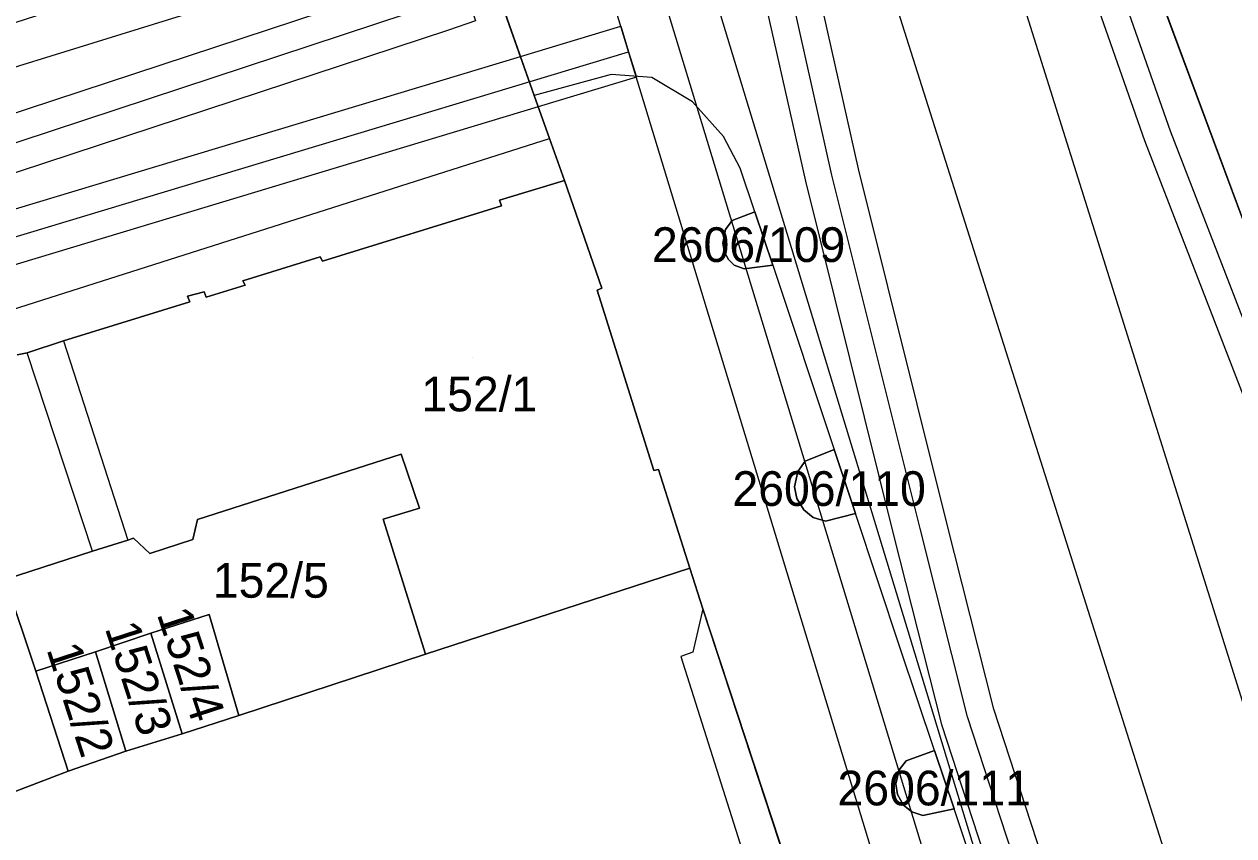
# Model space of a CAD drawing. Extents: x -263423 to -261326, y -1240067 to -1237864.
# Drawn here: x -262739.6 to -262669.9, y -1239931.7 to -1239884.9 of the extents above; entities that cross this region are included whole.
import ezdxf

# ---------------------------------------------------------------- set-up
doc = ezdxf.new("R2010")
doc.units = 0
for name, color, linetype in [('body_kn', 7, 'Continuous'), ('kladpar_druhypozemkov', 7, 'Continuous'), ('kladpar_hranice', 7, 'Continuous'), ('kladpar_parcelnecisla', 7, 'Continuous'), ('kladpar_plochy', 7, 'Continuous'), ('tarchy_linie', 7, 'Continuous'), ('zappar_hrandruhpozemk', 7, 'Continuous')]:
    doc.layers.add(name, color=color, linetype=linetype)

msp = doc.modelspace()

# ---------------------------------------------------------------- linework, layer by layer
at = {"layer": 'body_kn'}
for p, q in [((-262715.16, -1239885.25), (-262715.16, -1239885.25)), ((-262705.21, -1239885.03), (-262705.21, -1239885.03)), ((-262704.77, -1239886.5), (-262704.77, -1239886.5)), ((-262711.01, -1239886.77), (-262711.01, -1239886.77)), ((-262705.77, -1239887.81), (-262705.77, -1239887.81)), ((-262704.32, -1239887.97), (-262704.32, -1239887.97)), ((-262703.42, -1239887.99), (-262703.42, -1239887.99)), ((-262710.21, -1239889.03), (-262710.21, -1239889.03)), ((-262701.09, -1239889.38), (-262701.09, -1239889.38)), ((-262709.98, -1239889.68), (-262709.98, -1239889.68)), ((-262709.34, -1239891.5), (-262709.34, -1239891.5)), ((-262699.29, -1239891.39), (-262699.29, -1239891.39)), ((-262675.02, -1239891.62), (-262675.02, -1239891.62)), ((-262673.54, -1239891.07), (-262673.54, -1239891.07)), ((-262698.33, -1239893.21), (-262698.33, -1239893.21)), ((-262693.04, -1239893.61), (-262693.04, -1239893.61)), ((-262691.51, -1239893.25), (-262691.51, -1239893.25)), ((-262708.46, -1239893.93), (-262708.46, -1239893.93)), ((-262694.57, -1239893.97), (-262694.57, -1239893.97)), ((-262712.22, -1239895.06), (-262712.22, -1239895.06)), ((-262712.1, -1239895.38), (-262712.1, -1239895.38)), ((-262697.49, -1239895.73), (-262697.49, -1239895.73)), ((-262697.49, -1239895.73), (-262697.49, -1239895.73)), ((-262698.79, -1239896.22), (-262698.79, -1239896.22)), ((-262699.18, -1239896.75), (-262699.18, -1239896.75)), ((-262699.34, -1239897.54), (-262699.34, -1239897.54)), ((-262722.55, -1239898.33), (-262722.55, -1239898.33)), ((-262722.43, -1239898.58), (-262722.43, -1239898.58)), ((-262699.23, -1239898.06), (-262699.23, -1239898.06)), ((-262699, -1239898.48), (-262699, -1239898.48)), ((-262698.68, -1239898.8), (-262698.68, -1239898.8)), ((-262698.11, -1239899.02), (-262698.11, -1239899.02)), ((-262696.46, -1239898.81), (-262696.46, -1239898.81)), ((-262696.46, -1239898.81), (-262696.46, -1239898.81)), ((-262727.02, -1239899.71), (-262727.02, -1239899.71)), ((-262726.89, -1239899.96), (-262726.89, -1239899.96)), ((-262730.21, -1239900.59), (-262730.21, -1239900.59)), ((-262729.25, -1239900.34), (-262729.25, -1239900.34)), ((-262729.13, -1239900.65), (-262729.13, -1239900.65)), ((-262706.58, -1239900.24), (-262706.58, -1239900.24)), ((-262706.32, -1239900.12), (-262706.32, -1239900.12)), ((-262730.08, -1239900.91), (-262730.08, -1239900.91)), ((-262730.08, -1239900.91), (-262730.08, -1239900.91)), ((-262737.35, -1239903.17), (-262737.35, -1239903.17)), ((-262737.35, -1239903.17), (-262737.35, -1239903.17)), ((-262739.46, -1239903.86), (-262739.46, -1239903.86)), ((-262717.89, -1239909.69), (-262717.89, -1239909.69)), ((-262692.92, -1239909.43), (-262692.92, -1239909.43)), ((-262694.58, -1239910.1), (-262694.58, -1239910.1)), ((-262703.31, -1239910.64), (-262703.31, -1239910.64)), ((-262703.05, -1239910.58), (-262703.05, -1239910.58)), ((-262695, -1239910.69), (-262695, -1239910.69)), ((-262695.2, -1239911.57), (-262695.2, -1239911.57)), ((-262695.07, -1239912.26), (-262695.07, -1239912.26)), ((-262716.82, -1239912.81), (-262716.82, -1239912.81)), ((-262694.67, -1239912.91), (-262694.67, -1239912.91)), ((-262691.69, -1239913.11), (-262691.69, -1239913.11)), ((-262691.69, -1239913.11), (-262691.69, -1239913.11)), ((-262729.63, -1239913.46), (-262729.63, -1239913.46)), ((-262718.93, -1239913.44), (-262718.93, -1239913.44)), ((-262694.12, -1239913.34), (-262694.12, -1239913.34)), ((-262693.42, -1239913.56), (-262693.42, -1239913.56)), ((-262686.43, -1239913.6), (-262686.43, -1239913.6)), ((-262733.64, -1239914.65), (-262733.64, -1239914.65)), ((-262733.32, -1239914.53), (-262733.32, -1239914.53)), ((-262729.89, -1239914.61), (-262729.89, -1239914.61)), ((-262689.49, -1239914.36), (-262689.49, -1239914.36)), ((-262687.96, -1239913.98), (-262687.96, -1239913.98)), ((-262735.68, -1239915.28), (-262735.68, -1239915.28)), ((-262735.68, -1239915.28), (-262735.68, -1239915.28)), ((-262732.37, -1239915.42), (-262732.37, -1239915.42)), ((-262701.23, -1239916.26), (-262701.23, -1239916.26)), ((-262700.48, -1239918.62), (-262700.48, -1239918.62)), ((-262700.48, -1239918.62), (-262700.48, -1239918.62)), ((-262728.95, -1239918.94), (-262728.95, -1239918.94)), ((-262728.95, -1239918.94), (-262728.95, -1239918.94)), ((-262732.33, -1239920.01), (-262732.33, -1239920.01)), ((-262732.33, -1239920.01), (-262732.33, -1239920.01)), ((-262689.1, -1239920.88), (-262689.1, -1239920.88)), ((-262735.52, -1239921.08), (-262735.52, -1239921.08)), ((-262735.52, -1239921.08), (-262735.52, -1239921.08)), ((-262716.48, -1239921.23), (-262716.48, -1239921.23)), ((-262701.76, -1239921.35), (-262701.76, -1239921.35)), ((-262701.06, -1239921.1), (-262701.06, -1239921.1)), ((-262738.96, -1239922.21), (-262738.96, -1239922.21)), ((-262683.71, -1239924.4), (-262683.71, -1239924.4)), ((-262727.25, -1239924.75), (-262727.25, -1239924.75)), ((-262685.22, -1239924.84), (-262685.22, -1239924.84)), ((-262686.73, -1239925.28), (-262686.73, -1239925.28)), ((-262730.51, -1239925.82), (-262730.51, -1239925.82)), ((-262733.76, -1239926.82), (-262733.76, -1239926.82)), ((-262687.12, -1239926.78), (-262687.12, -1239926.78)), ((-262687.12, -1239926.78), (-262687.12, -1239926.78)), ((-262689.16, -1239927.9), (-262689.16, -1239927.9)), ((-262688.76, -1239927.38), (-262688.76, -1239927.38)), ((-262737.08, -1239927.96), (-262737.08, -1239927.96)), ((-262689.36, -1239928.69), (-262689.36, -1239928.69)), ((-262689.26, -1239929.32), (-262689.26, -1239929.32)), ((-262688.92, -1239929.92), (-262688.92, -1239929.92)), ((-262688.44, -1239930.32), (-262688.44, -1239930.32)), ((-262687.81, -1239930.53), (-262687.81, -1239930.53)), ((-262686, -1239930.14), (-262686, -1239930.14)), ((-262686, -1239930.14), (-262686, -1239930.14))]:
    msp.add_line(p, q, dxfattribs=at)
at = {"layer": 'kladpar_druhypozemkov'}
for p, q in [((-262697.94, -1239897.21), (-262697.94, -1239897.21)), ((-262713.76, -1239904.13), (-262713.76, -1239904.13)), ((-262693.68, -1239911.14), (-262693.68, -1239911.14)), ((-262724.36, -1239915.87), (-262724.36, -1239915.87)), ((-262728.56, -1239922.93), (-262728.56, -1239922.93)), ((-262731.76, -1239924.23), (-262731.76, -1239924.23)), ((-262734.96, -1239925.33), (-262734.96, -1239925.33)), ((-262687.85, -1239928.44), (-262687.85, -1239928.44))]:
    msp.add_line(p, q, dxfattribs=at)
at = {"layer": 'kladpar_hranice'}
for points in [[(-262686.78, -1239809.35), (-262684.33, -1239817.9), (-262683.63, -1239817.77), (-262683.37, -1239818.54), (-262682.24, -1239822.49), (-262682.63, -1239822.68), (-262680.93, -1239828.11), (-262680.48, -1239828.04), (-262679.23, -1239832.57), (-262679.61, -1239832.76), (-262677.91, -1239838.12), (-262677.6, -1239838.06), (-262676.46, -1239841.89), (-262671.94, -1239857.45), (-262672.03, -1239861.72), (-262672.37, -1239870.17), (-262672.59, -1239875.61), (-262673.93, -1239876.17), (-262674.7, -1239876.81), (-262675.21, -1239877.57), (-262675.53, -1239878.4), (-262675.54, -1239879.16), (-262675.41, -1239879.86), (-262662.51, -1239914.58)], [(-262662.51, -1239914.58), (-262675.41, -1239879.86), (-262675.54, -1239879.16), (-262675.53, -1239878.4), (-262675.21, -1239877.57), (-262674.7, -1239876.81), (-262673.93, -1239876.17), (-262672.59, -1239875.61), (-262666.09, -1239872.77)], [(-262740.08, -1239884.8), (-262714.44, -1239876.51), (-262713.68, -1239879.19), (-262710.21, -1239889.03), (-262709.34, -1239891.5), (-262708.46, -1239893.93), (-262712.22, -1239895.06), (-262712.1, -1239895.38), (-262722.43, -1239898.58), (-262722.55, -1239898.33), (-262727.02, -1239899.71), (-262726.89, -1239899.96), (-262729.13, -1239900.65), (-262729.25, -1239900.34), (-262730.21, -1239900.59), (-262730.08, -1239900.91), (-262737.35, -1239903.17), (-262739.46, -1239903.86), (-262740.03, -1239903.98)], [(-262684.65, -1239967.69), (-262689.79, -1239950.72), (-262689.98, -1239950.78), (-262693.06, -1239941.27), (-262693.82, -1239938.85), (-262695.07, -1239935.08), (-262700.48, -1239918.62), (-262701.23, -1239916.26), (-262703.05, -1239910.58), (-262703.31, -1239910.64), (-262706.58, -1239900.24), (-262706.32, -1239900.12), (-262708.46, -1239893.93), (-262709.34, -1239891.5), (-262710.21, -1239889.03), (-262713.68, -1239879.19)], [(-262730.08, -1239900.91), (-262730.21, -1239900.59), (-262729.25, -1239900.34), (-262729.13, -1239900.65), (-262726.89, -1239899.96), (-262727.02, -1239899.71), (-262722.55, -1239898.33), (-262722.43, -1239898.58), (-262712.1, -1239895.38), (-262712.22, -1239895.06), (-262708.46, -1239893.93), (-262706.32, -1239900.12), (-262706.58, -1239900.24), (-262703.31, -1239910.64), (-262703.05, -1239910.58), (-262701.23, -1239916.26), (-262716.48, -1239921.23), (-262718.93, -1239913.44), (-262716.82, -1239912.81), (-262717.89, -1239909.69), (-262729.63, -1239913.46), (-262729.89, -1239914.61), (-262732.37, -1239915.42), (-262733.32, -1239914.53), (-262733.64, -1239914.65), (-262735.68, -1239915.28), (-262740.72, -1239916.92)], [(-262696.46, -1239898.81), (-262698.11, -1239899.02), (-262698.68, -1239898.8), (-262699, -1239898.48), (-262699.23, -1239898.06), (-262699.34, -1239897.54), (-262699.18, -1239896.75), (-262698.79, -1239896.22), (-262697.49, -1239895.73), (-262696.46, -1239898.81)], [(-262698.11, -1239899.02), (-262696.46, -1239898.81), (-262697.49, -1239895.73), (-262698.79, -1239896.22), (-262699.18, -1239896.75), (-262699.34, -1239897.54), (-262699.23, -1239898.06), (-262699, -1239898.48), (-262698.68, -1239898.8), (-262698.11, -1239899.02)], [(-262740.03, -1239903.98), (-262739.46, -1239903.86), (-262737.35, -1239903.17), (-262730.08, -1239900.91)], [(-262744.05, -1239905.43), (-262740.72, -1239916.92), (-262738.96, -1239922.21), (-262737.08, -1239927.96), (-262746.14, -1239931.42), (-262747.58, -1239927.27), (-262757.35, -1239930.42), (-262757.91, -1239928.69), (-262759.19, -1239924.62), (-262759.48, -1239923.69), (-262763.31, -1239911.53), (-262744.05, -1239905.43)], [(-262740.72, -1239916.92), (-262735.68, -1239915.28), (-262733.64, -1239914.65), (-262733.32, -1239914.53), (-262732.37, -1239915.42), (-262729.89, -1239914.61), (-262729.63, -1239913.46), (-262717.89, -1239909.69), (-262716.82, -1239912.81), (-262718.93, -1239913.44), (-262716.48, -1239921.23), (-262727.25, -1239924.75), (-262728.95, -1239918.94), (-262732.33, -1239920.01), (-262735.52, -1239921.08), (-262738.96, -1239922.21), (-262740.72, -1239916.92)], [(-262691.69, -1239913.11), (-262693.42, -1239913.56), (-262694.12, -1239913.34), (-262694.67, -1239912.91), (-262695.07, -1239912.26), (-262695.2, -1239911.57), (-262695, -1239910.69), (-262694.58, -1239910.1), (-262692.92, -1239909.43), (-262691.69, -1239913.11)], [(-262693.42, -1239913.56), (-262691.69, -1239913.11), (-262692.92, -1239909.43), (-262694.58, -1239910.1), (-262695, -1239910.69), (-262695.2, -1239911.57), (-262695.07, -1239912.26), (-262694.67, -1239912.91), (-262694.12, -1239913.34), (-262693.42, -1239913.56)], [(-262746.14, -1239931.42), (-262737.08, -1239927.96), (-262733.76, -1239926.82), (-262730.51, -1239925.82), (-262727.25, -1239924.75), (-262716.48, -1239921.23), (-262701.23, -1239916.26), (-262700.48, -1239918.62), (-262695.07, -1239935.08), (-262693.82, -1239938.85), (-262693.06, -1239941.27), (-262689.98, -1239950.78), (-262689.79, -1239950.72), (-262684.65, -1239967.69)], [(-262728.95, -1239918.94), (-262727.25, -1239924.75), (-262730.51, -1239925.82), (-262732.33, -1239920.01), (-262728.95, -1239918.94)], [(-262732.33, -1239920.01), (-262730.51, -1239925.82), (-262733.76, -1239926.82), (-262735.52, -1239921.08), (-262732.33, -1239920.01)], [(-262735.52, -1239921.08), (-262733.76, -1239926.82), (-262737.08, -1239927.96), (-262738.96, -1239922.21), (-262735.52, -1239921.08)], [(-262686, -1239930.14), (-262687.81, -1239930.53), (-262688.44, -1239930.32), (-262688.92, -1239929.92), (-262689.26, -1239929.32), (-262689.36, -1239928.69), (-262689.16, -1239927.9), (-262688.76, -1239927.38), (-262687.12, -1239926.78), (-262686, -1239930.14)], [(-262687.81, -1239930.53), (-262686, -1239930.14), (-262687.12, -1239926.78), (-262688.76, -1239927.38), (-262689.16, -1239927.9), (-262689.36, -1239928.69), (-262689.26, -1239929.32), (-262688.92, -1239929.92), (-262688.44, -1239930.32), (-262687.81, -1239930.53)]]:
    msp.add_lwpolyline(points, dxfattribs=at)
at = {"layer": 'kladpar_plochy'}
for p, q in [((-262710.21, -1239889.03), (-262713.68, -1239879.19)), ((-262662.51, -1239914.58), (-262675.41, -1239879.86)), ((-262675.41, -1239879.86), (-262662.51, -1239914.58)), ((-262709.34, -1239891.5), (-262710.21, -1239889.03)), ((-262708.46, -1239893.93), (-262709.34, -1239891.5)), ((-262706.32, -1239900.12), (-262708.46, -1239893.93)), ((-262697.49, -1239895.73), (-262698.79, -1239896.22)), ((-262696.46, -1239898.81), (-262697.49, -1239895.73)), ((-262698.79, -1239896.22), (-262699.18, -1239896.75)), ((-262699.18, -1239896.75), (-262699.34, -1239897.54)), ((-262699.34, -1239897.54), (-262699.23, -1239898.06)), ((-262699.23, -1239898.06), (-262699, -1239898.48)), ((-262699, -1239898.48), (-262698.68, -1239898.8)), ((-262698.68, -1239898.8), (-262698.11, -1239899.02)), ((-262698.11, -1239899.02), (-262696.46, -1239898.81)), ((-262706.58, -1239900.24), (-262706.32, -1239900.12)), ((-262703.31, -1239910.64), (-262706.58, -1239900.24)), ((-262692.92, -1239909.43), (-262694.58, -1239910.1)), ((-262691.69, -1239913.11), (-262692.92, -1239909.43)), ((-262694.58, -1239910.1), (-262695, -1239910.69)), ((-262703.05, -1239910.58), (-262703.31, -1239910.64)), ((-262701.23, -1239916.26), (-262703.05, -1239910.58)), ((-262695, -1239910.69), (-262695.2, -1239911.57)), ((-262695.2, -1239911.57), (-262695.07, -1239912.26)), ((-262695.07, -1239912.26), (-262694.67, -1239912.91)), ((-262694.67, -1239912.91), (-262694.12, -1239913.34)), ((-262693.42, -1239913.56), (-262691.69, -1239913.11)), ((-262694.12, -1239913.34), (-262693.42, -1239913.56)), ((-262700.48, -1239918.62), (-262701.23, -1239916.26)), ((-262695.07, -1239935.08), (-262700.48, -1239918.62)), ((-262687.12, -1239926.78), (-262688.76, -1239927.38)), ((-262686, -1239930.14), (-262687.12, -1239926.78)), ((-262689.16, -1239927.9), (-262689.36, -1239928.69)), ((-262688.76, -1239927.38), (-262689.16, -1239927.9)), ((-262689.36, -1239928.69), (-262689.26, -1239929.32)), ((-262689.26, -1239929.32), (-262688.92, -1239929.92)), ((-262688.92, -1239929.92), (-262688.44, -1239930.32)), ((-262688.44, -1239930.32), (-262687.81, -1239930.53)), ((-262687.81, -1239930.53), (-262686, -1239930.14))]:
    msp.add_line(p, q, dxfattribs=at)
for points in [[(-262740.08, -1239884.8), (-262714.44, -1239876.51), (-262713.68, -1239879.19), (-262710.21, -1239889.03), (-262709.34, -1239891.5), (-262708.46, -1239893.93), (-262712.22, -1239895.06), (-262712.1, -1239895.38), (-262722.43, -1239898.58), (-262722.55, -1239898.33), (-262727.02, -1239899.71), (-262726.89, -1239899.96), (-262729.13, -1239900.65), (-262729.25, -1239900.34), (-262730.21, -1239900.59), (-262730.08, -1239900.91), (-262737.35, -1239903.17), (-262739.46, -1239903.86), (-262740.03, -1239903.98)], [(-262740.03, -1239903.98), (-262739.46, -1239903.86), (-262737.35, -1239903.17), (-262730.08, -1239900.91), (-262730.21, -1239900.59), (-262729.25, -1239900.34), (-262729.13, -1239900.65), (-262726.89, -1239899.96), (-262727.02, -1239899.71), (-262722.55, -1239898.33), (-262722.43, -1239898.58), (-262712.1, -1239895.38), (-262712.22, -1239895.06), (-262708.46, -1239893.93), (-262706.32, -1239900.12), (-262706.58, -1239900.24), (-262703.31, -1239910.64), (-262703.05, -1239910.58), (-262701.23, -1239916.26), (-262716.48, -1239921.23), (-262718.93, -1239913.44), (-262716.82, -1239912.81), (-262717.89, -1239909.69), (-262729.63, -1239913.46), (-262729.89, -1239914.61), (-262732.37, -1239915.42), (-262733.32, -1239914.53), (-262733.64, -1239914.65), (-262735.68, -1239915.28), (-262740.72, -1239916.92)], [(-262746.14, -1239931.42), (-262737.08, -1239927.96), (-262733.76, -1239926.82), (-262730.51, -1239925.82), (-262727.25, -1239924.75), (-262716.48, -1239921.23), (-262701.23, -1239916.26), (-262700.48, -1239918.62), (-262695.07, -1239935.08), (-262693.82, -1239938.85), (-262693.06, -1239941.27), (-262689.98, -1239950.78), (-262689.79, -1239950.72), (-262684.65, -1239967.69)]]:
    msp.add_lwpolyline(points, dxfattribs=at)
for points in [[(-262696.46, -1239898.81), (-262698.11, -1239899.02), (-262698.68, -1239898.8), (-262699, -1239898.48), (-262699.23, -1239898.06), (-262699.34, -1239897.54), (-262699.18, -1239896.75), (-262698.79, -1239896.22), (-262697.49, -1239895.73)], [(-262744.05, -1239905.43), (-262740.72, -1239916.92), (-262738.96, -1239922.21), (-262737.08, -1239927.96), (-262746.14, -1239931.42), (-262747.58, -1239927.27), (-262757.35, -1239930.42), (-262757.91, -1239928.69), (-262759.19, -1239924.62), (-262759.48, -1239923.69), (-262763.31, -1239911.53)], [(-262740.72, -1239916.92), (-262735.68, -1239915.28), (-262733.64, -1239914.65), (-262733.32, -1239914.53), (-262732.37, -1239915.42), (-262729.89, -1239914.61), (-262729.63, -1239913.46), (-262717.89, -1239909.69), (-262716.82, -1239912.81), (-262718.93, -1239913.44), (-262716.48, -1239921.23), (-262727.25, -1239924.75), (-262728.95, -1239918.94), (-262732.33, -1239920.01), (-262735.52, -1239921.08), (-262738.96, -1239922.21)], [(-262691.69, -1239913.11), (-262693.42, -1239913.56), (-262694.12, -1239913.34), (-262694.67, -1239912.91), (-262695.07, -1239912.26), (-262695.2, -1239911.57), (-262695, -1239910.69), (-262694.58, -1239910.1), (-262692.92, -1239909.43)], [(-262728.95, -1239918.94), (-262727.25, -1239924.75), (-262730.51, -1239925.82), (-262732.33, -1239920.01)], [(-262732.33, -1239920.01), (-262730.51, -1239925.82), (-262733.76, -1239926.82), (-262735.52, -1239921.08)], [(-262735.52, -1239921.08), (-262733.76, -1239926.82), (-262737.08, -1239927.96), (-262738.96, -1239922.21)], [(-262686, -1239930.14), (-262687.81, -1239930.53), (-262688.44, -1239930.32), (-262688.92, -1239929.92), (-262689.26, -1239929.32), (-262689.36, -1239928.69), (-262689.16, -1239927.9), (-262688.76, -1239927.38), (-262687.12, -1239926.78)]]:
    msp.add_lwpolyline(points, close=True, dxfattribs=at)
at = {"layer": 'tarchy_linie'}
for points in [[(-262657.08, -1239929.21), (-262646.38, -1239963), (-262674.82, -1239975.1), (-262703.83, -1239879.78), (-262739.61, -1239778.33), (-262778.19, -1239688.87), (-262817.29, -1239598.81)], [(-262700.29, -1239764.57), (-262673.55, -1239867.4), (-262671.15, -1239874.98), (-262672.59, -1239875.61), (-262673.88, -1239876.15), (-262673.93, -1239876.17), (-262674.7, -1239876.81), (-262675.21, -1239877.57), (-262675.53, -1239878.4), (-262675.54, -1239879.16), (-262675.41, -1239879.86), (-262662.51, -1239914.58), (-262657.08, -1239929.21), (-262650.11, -1239948.02), (-262649.29, -1239949.42), (-262648.47, -1239950.57), (-262647.52, -1239951.53), (-262646.71, -1239952.19), (-262642.79, -1239964.57), (-262676.62, -1239978.96), (-262706.54, -1239880.67), (-262742.27, -1239779.37)], [(-262733.86, -1239786.06), (-262731.31, -1239790.5), (-262727.77, -1239796.86), (-262723.05, -1239806.16), (-262717.47, -1239818.88), (-262715.31, -1239824.82), (-262709.31, -1239838.88), (-262708.04, -1239840.99), (-262702.91, -1239857), (-262700.03, -1239870.07), (-262696.82, -1239883.99), (-262694.57, -1239893.97), (-262689.49, -1239914.36), (-262686.73, -1239925.28), (-262678.36, -1239950.89), (-262673.78, -1239965.52), (-262673.54, -1239968), (-262672.3, -1239970.93), (-262673.02, -1239971.24), (-262701.12, -1239878.89), (-262733.86, -1239786.06)], [(-262701.41, -1239808.43), (-262691.04, -1239850.16), (-262687.88, -1239853.77), (-262683.02, -1239868.8), (-262675.02, -1239891.62), (-262660.7, -1239928.6), (-262653.54, -1239953.87), (-262651.61, -1239958.73), (-262670.45, -1239967.28), (-262670.68, -1239964.9), (-262675.36, -1239949.93), (-262683.71, -1239924.4), (-262686.43, -1239913.6), (-262691.51, -1239893.25), (-262693.74, -1239883.29), (-262696.95, -1239869.37), (-262699.87, -1239856.18), (-262705.16, -1239839.69), (-262706.49, -1239837.44), (-262712.37, -1239823.66), (-262714.55, -1239817.7), (-262720.21, -1239804.82)], [(-262699.88, -1239808.04), (-262689.6, -1239849.41), (-262686.48, -1239852.98), (-262681.53, -1239868.3), (-262673.54, -1239891.07), (-262659.2, -1239928.1), (-262652.05, -1239953.36), (-262649.56, -1239959.61), (-262671.22, -1239969.44), (-262672, -1239967.61), (-262672.23, -1239965.21), (-262676.86, -1239950.41), (-262685.22, -1239924.84), (-262687.96, -1239913.98), (-262693.04, -1239893.61), (-262695.28, -1239883.64), (-262698.49, -1239869.72), (-262701.39, -1239856.59), (-262706.6, -1239840.34), (-262707.9, -1239838.16), (-262713.84, -1239824.24), (-262716.01, -1239818.29), (-262721.63, -1239805.49)], [(-262744.13, -1239891.33), (-262716.19, -1239882.12), (-262714.62, -1239881.6), (-262713.59, -1239884.73), (-262715.16, -1239885.25), (-262743.09, -1239894.45)], [(-262823.42, -1239920.25), (-262783.59, -1239906.44), (-262743.61, -1239892.89), (-262715.67, -1239883.68)], [(-262759.96, -1239901.53), (-262711.01, -1239886.77), (-262705.21, -1239885.03), (-262704.77, -1239886.5), (-262704.32, -1239887.97), (-262709.98, -1239889.68), (-262759.08, -1239904.49)], [(-262814.9, -1239918.94), (-262759.52, -1239903.01), (-262704.77, -1239886.5)]]:
    msp.add_lwpolyline(points, dxfattribs=at)
at = {"layer": 'zappar_hrandruhpozemk'}
for p, q in [((-262686.99, -1239867.88), (-262665.81, -1239935.33)), ((-262672.47, -1239936.95), (-262693.57, -1239870.45)), ((-262705.77, -1239887.81), (-262710.21, -1239889.03)), ((-262703.42, -1239887.99), (-262705.77, -1239887.81)), ((-262696.46, -1239898.81), (-262692.92, -1239909.43)), ((-262737.35, -1239903.17), (-262733.64, -1239914.65)), ((-262735.68, -1239915.28), (-262739.46, -1239903.86)), ((-262701.76, -1239921.35), (-262697.68, -1239934.24)), ((-262677.38, -1239955.88), (-262686, -1239930.14))]:
    msp.add_line(p, q, dxfattribs=at)
for points in [[(-262713.68, -1239879.19), (-262764.39, -1239894.89), (-262811.6, -1239909.59)], [(-262697.49, -1239895.73), (-262698.33, -1239893.21), (-262699.29, -1239891.39), (-262701.09, -1239889.38), (-262703.42, -1239887.99)], [(-262808.92, -1239923.24), (-262757.94, -1239906.96), (-262709.34, -1239891.5)], [(-262687.12, -1239926.78), (-262689.1, -1239920.88), (-262691.69, -1239913.11)], [(-262700.48, -1239918.62), (-262701.06, -1239921.1), (-262701.76, -1239921.35)]]:
    msp.add_lwpolyline(points, dxfattribs=at)

# ---------------------------------------------------------------- texts
at = {"layer": 'kladpar_parcelnecisla'}
for s, p in [('2606/109', (-262703.422, -1239898.62)), ('152/1', (-262716.722, -1239907.23)), ('2606/110', (-262698.782, -1239912.68)), ('152/5', (-262728.747, -1239917.97)), ('2606/111', (-262692.722, -1239929.94))]:
    msp.add_text(s, height=2, dxfattribs=at).set_placement(p)
for s, p in [('152/4', (-262731.986, -1239918.902)), ('152/3', (-262734.988, -1239919.715)), ('152/2', (-262738.353, -1239920.94))]:
    msp.add_text(s, height=2, rotation=288, dxfattribs=at).set_placement(p)

doc.saveas('drawing.dxf')
